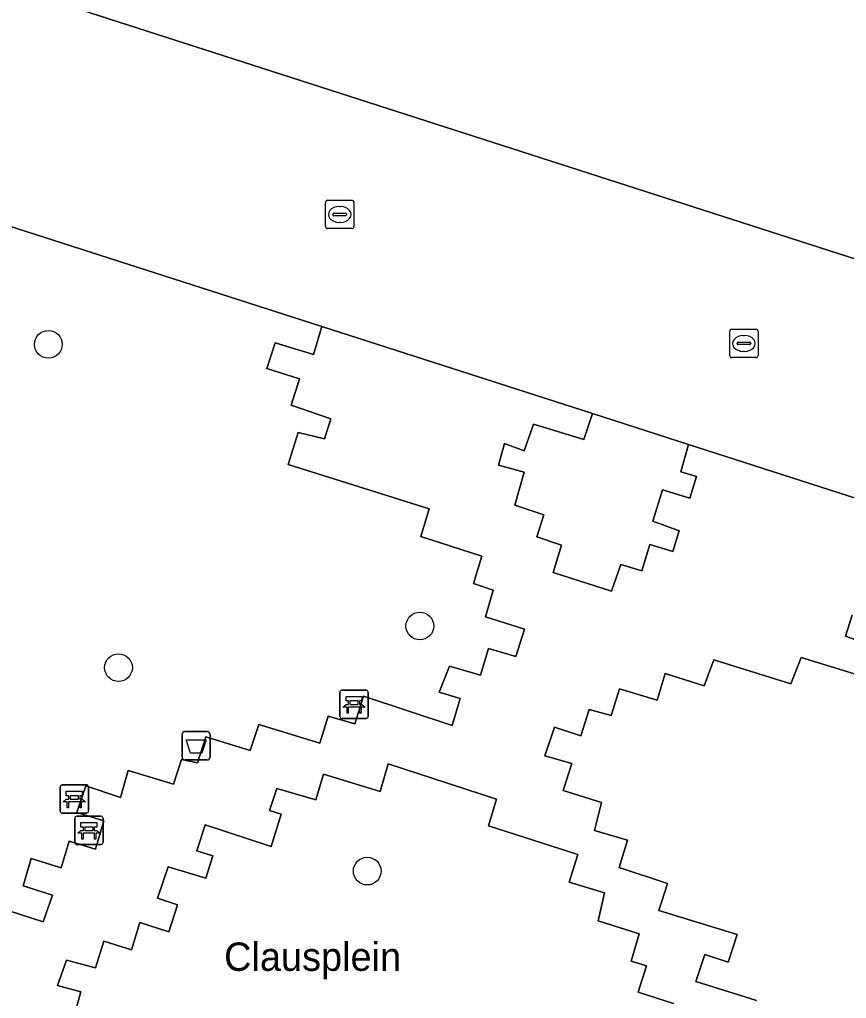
# Model space of a CAD drawing. Extents: x 160675 to 161153, y 383241 to 383714.
# Drawn here: x 161009.79 to 161038.96, y 383290.07 to 383324.6 of the extents above; entities that cross this region are included whole.
import ezdxf

# ---------------------------------------------------------------- set-up
doc = ezdxf.new("R2010")
doc.units = 0
for name, color, linetype in [('IMGEO_Afvalbak', 7, 'Continuous'), ('IMGEO_Bank', 7, 'Continuous'), ('IMGEO_Boom', 7, 'Continuous'), ('IMGEO_Groenvoorziening', 7, 'Continuous'), ('IMGEO_Kolk', 7, 'Continuous'), ('IMGEO_Openbare_ruimte_label', 7, 'Continuous'), ('IMGEO_Pand', 7, 'Continuous'), ('IMGEO_Voetpad_open', 7, 'Continuous')]:
    doc.layers.add(name, color=color, linetype=linetype)

msp = doc.modelspace()

# ---------------------------------------------------------------- linework, layer by layer
at = {"layer": 'IMGEO_Afvalbak'}
for p, q in [((161015.621, 383299.483), (161016.411, 383299.483)), ((161016.411, 383299.483), (161015.621, 383299.483)), ((161015.521, 383298.583), (161015.521, 383299.383)), ((161015.521, 383299.383), (161015.521, 383298.583)), ((161016.511, 383299.383), (161016.511, 383298.583)), ((161016.511, 383298.583), (161016.511, 383299.383)), ((161016.411, 383298.483), (161015.621, 383298.483)), ((161015.621, 383298.483), (161016.411, 383298.483))]:
    msp.add_line(p, q, dxfattribs=at)
msp.add_lwpolyline([(161015.664, 383299.197), (161016.368, 383299.197), (161016.219, 383298.727), (161015.813, 383298.727), (161015.664, 383299.197)], dxfattribs=at)
for centre, start, end in [((161015.621, 383299.383), 90, 180), ((161015.621, 383299.383), 90, 180), ((161016.411, 383299.383), 0, 90), ((161016.411, 383299.383), 360, 90), ((161015.621, 383298.583), 180, 270), ((161015.621, 383298.583), 180, 270), ((161016.411, 383298.583), 270, 0), ((161016.411, 383298.583), 270, 0)]:
    msp.add_arc(centre, 0.1, start, end, dxfattribs=at)
at = {"layer": 'IMGEO_Bank'}
for p, q in [((161021.086, 383300.021), (161021.086, 383300.862)), ((161021.086, 383300.862), (161021.086, 383300.021)), ((161021.161, 383300.946), (161022.002, 383300.946)), ((161022.002, 383300.946), (161021.161, 383300.946)), ((161022.086, 383300.871), (161022.086, 383300.03)), ((161022.086, 383300.03), (161022.086, 383300.871)), ((161021.395, 383300.452), (161021.395, 383300.558)), ((161021.439, 383300.558), (161021.439, 383300.452)), ((161021.727, 383300.564), (161021.445, 383300.564)), ((161021.445, 383300.446), (161021.727, 383300.446)), ((161021.733, 383300.452), (161021.733, 383300.558)), ((161021.777, 383300.558), (161021.777, 383300.452)), ((161021.783, 383300.344), (161021.39, 383300.344)), ((161022.011, 383299.946), (161021.17, 383299.946)), ((161021.17, 383299.946), (161022.011, 383299.946)), ((161011.218, 383296.681), (161011.218, 383297.522)), ((161011.218, 383297.522), (161011.218, 383296.681)), ((161011.293, 383297.606), (161012.134, 383297.606)), ((161012.134, 383297.606), (161011.293, 383297.606)), ((161012.218, 383297.531), (161012.218, 383296.69)), ((161012.218, 383296.69), (161012.218, 383297.531)), ((161011.915, 383297.004), (161011.522, 383297.004)), ((161011.527, 383297.112), (161011.527, 383297.218)), ((161011.571, 383297.218), (161011.571, 383297.112)), ((161011.859, 383297.224), (161011.577, 383297.224)), ((161011.577, 383297.106), (161011.859, 383297.106)), ((161011.865, 383297.112), (161011.865, 383297.218)), ((161011.909, 383297.218), (161011.909, 383297.112)), ((161012.143, 383296.606), (161011.302, 383296.606)), ((161011.302, 383296.606), (161012.143, 383296.606)), ((161011.733, 383295.576), (161011.733, 383296.417)), ((161011.733, 383296.417), (161011.733, 383295.576)), ((161011.808, 383296.501), (161012.649, 383296.501)), ((161012.649, 383296.501), (161011.808, 383296.501)), ((161012.733, 383296.426), (161012.733, 383295.585)), ((161012.733, 383295.585), (161012.733, 383296.426)), ((161012.042, 383296.007), (161012.042, 383296.113)), ((161012.086, 383296.113), (161012.086, 383296.007)), ((161012.374, 383296.119), (161012.092, 383296.119)), ((161012.092, 383296.001), (161012.374, 383296.001)), ((161012.38, 383296.007), (161012.38, 383296.113)), ((161012.424, 383296.113), (161012.424, 383296.007)), ((161012.43, 383295.899), (161012.037, 383295.899)), ((161012.658, 383295.501), (161011.817, 383295.501)), ((161011.817, 383295.501), (161012.658, 383295.501))]:
    msp.add_line(p, q, dxfattribs=at)
for points in [[(161021.333, 383300.344), (161021.191, 383300.344), (161021.303, 383300.446), (161021.389, 383300.446)], [(161021.389, 383300.564), (161021.303, 383300.564), (161021.303, 383300.725), (161021.866, 383300.725), (161021.866, 383300.564), (161021.783, 383300.564)], [(161021.783, 383300.446), (161021.866, 383300.446), (161021.978, 383300.344), (161021.839, 383300.344)], [(161021.383, 383300.337), (161021.383, 383300.13), (161021.34, 383300.13), (161021.34, 383300.337)], [(161021.833, 383300.337), (161021.833, 383300.13), (161021.789, 383300.13), (161021.789, 383300.337)], [(161011.521, 383297.224), (161011.435, 383297.224), (161011.435, 383297.385), (161011.998, 383297.385), (161011.998, 383297.224), (161011.915, 383297.224)], [(161011.465, 383297.004), (161011.323, 383297.004), (161011.435, 383297.106), (161011.521, 383297.106)], [(161011.515, 383296.997), (161011.515, 383296.79), (161011.472, 383296.79), (161011.472, 383296.997)], [(161011.915, 383297.106), (161011.998, 383297.106), (161012.11, 383297.004), (161011.971, 383297.004)], [(161011.965, 383296.997), (161011.965, 383296.79), (161011.921, 383296.79), (161011.921, 383296.997)], [(161011.98, 383295.899), (161011.838, 383295.899), (161011.95, 383296.001), (161012.036, 383296.001)], [(161012.036, 383296.119), (161011.95, 383296.119), (161011.95, 383296.28), (161012.513, 383296.28), (161012.513, 383296.119), (161012.43, 383296.119)], [(161012.43, 383296.001), (161012.513, 383296.001), (161012.625, 383295.899), (161012.486, 383295.899)], [(161012.03, 383295.892), (161012.03, 383295.685), (161011.987, 383295.685), (161011.987, 383295.892)], [(161012.48, 383295.892), (161012.48, 383295.685), (161012.436, 383295.685), (161012.436, 383295.892)]]:
    msp.add_lwpolyline(points, dxfattribs=at)
for centre, radius, start, end in [((161021.164, 383300.868), 0.0779, 92.4484, 184.2845), ((161021.164, 383300.868), 0.0779, 92.4484, 184.2845), ((161022.008, 383300.868), 0.0779, 2.4484, 94.2845), ((161022.008, 383300.868), 0.0779, 2.4484, 94.2845), ((161021.388, 383300.557), 0.00671, 2.8957, 87.1043), ((161021.388, 383300.453), 0.00671, 272.8957, 357.1043), ((161021.445, 383300.557), 0.00671, 92.8957, 177.1043), ((161021.445, 383300.453), 0.00671, 182.8957, 267.1043), ((161021.727, 383300.557), 0.00671, 2.8957, 87.1043), ((161021.727, 383300.453), 0.00671, 272.8957, 357.1043), ((161021.784, 383300.557), 0.00671, 92.8957, 177.1043), ((161021.784, 383300.453), 0.00671, 182.8957, 267.1043), ((161021.333, 383300.337), 0.00671, 2.8957, 87.1043), ((161021.39, 383300.337), 0.00671, 92.8957, 177.1043), ((161021.782, 383300.337), 0.00671, 2.8957, 87.1043), ((161021.839, 383300.337), 0.00671, 92.8957, 177.1043), ((161021.164, 383300.024), 0.0779, 182.4484, 274.2845), ((161021.164, 383300.024), 0.0779, 182.4484, 274.2845), ((161022.008, 383300.024), 0.0779, 272.4484, 4.2845), ((161022.008, 383300.024), 0.0779, 272.4484, 4.2845), ((161011.296, 383297.528), 0.0779, 92.4484, 184.2845), ((161011.296, 383297.528), 0.0779, 92.4484, 184.2845), ((161012.14, 383297.528), 0.0779, 2.4484, 94.2845), ((161012.14, 383297.528), 0.0779, 2.4484, 94.2845), ((161011.465, 383296.997), 0.00671, 2.8957, 87.1043), ((161011.522, 383296.997), 0.00671, 92.8957, 177.1043), ((161011.52, 383297.217), 0.00671, 2.8957, 87.1043), ((161011.52, 383297.113), 0.00671, 272.8957, 357.1043), ((161011.577, 383297.217), 0.00671, 92.8957, 177.1043), ((161011.577, 383297.113), 0.00671, 182.8957, 267.1043), ((161011.859, 383297.217), 0.00671, 2.8957, 87.1043), ((161011.859, 383297.113), 0.00671, 272.8957, 357.1043), ((161011.916, 383297.217), 0.00671, 92.8957, 177.1043), ((161011.916, 383297.113), 0.00671, 182.8957, 267.1043), ((161011.914, 383296.997), 0.00671, 2.8957, 87.1043), ((161011.971, 383296.997), 0.00671, 92.8957, 177.1043), ((161011.296, 383296.684), 0.0779, 182.4484, 274.2845), ((161011.296, 383296.684), 0.0779, 182.4484, 274.2845), ((161012.14, 383296.684), 0.0779, 272.4484, 4.2845), ((161012.14, 383296.684), 0.0779, 272.4484, 4.2845), ((161011.811, 383296.423), 0.0779, 92.4484, 184.2845), ((161011.811, 383296.423), 0.0779, 92.4484, 184.2845), ((161012.655, 383296.423), 0.0779, 2.4484, 94.2845), ((161012.655, 383296.423), 0.0779, 2.4484, 94.2845), ((161012.035, 383296.112), 0.00671, 2.8957, 87.1043), ((161012.035, 383296.008), 0.00671, 272.8957, 357.1043), ((161012.092, 383296.112), 0.00671, 92.8957, 177.1043), ((161012.092, 383296.008), 0.00671, 182.8957, 267.1043), ((161012.374, 383296.112), 0.00671, 2.8957, 87.1043), ((161012.374, 383296.008), 0.00671, 272.8957, 357.1043), ((161012.431, 383296.112), 0.00671, 92.8957, 177.1043), ((161012.431, 383296.008), 0.00671, 182.8957, 267.1043), ((161011.98, 383295.892), 0.00671, 2.8957, 87.1043), ((161012.037, 383295.892), 0.00671, 92.8957, 177.1043), ((161012.429, 383295.892), 0.00671, 2.8957, 87.1043), ((161012.486, 383295.892), 0.00671, 92.8957, 177.1043), ((161011.811, 383295.579), 0.0779, 182.4484, 274.2845), ((161011.811, 383295.579), 0.0779, 182.4484, 274.2845), ((161012.655, 383295.579), 0.0779, 272.4484, 4.2845), ((161012.655, 383295.579), 0.0779, 272.4484, 4.2845)]:
    msp.add_arc(centre, radius, start, end, dxfattribs=at)
at = {"layer": 'IMGEO_Boom'}
for centre in [(161010.8, 383313.141), (161023.908, 383303.206), (161013.277, 383301.742), (161022.051, 383294.563)]:
    msp.add_circle(centre, 0.489, dxfattribs=at)
at = {"layer": 'IMGEO_Groenvoorziening'}
for points in [[(161009.01, 383293.288), (161010.622, 383292.773), (161010.949, 383293.72), (161009.912, 383294.046), (161010.191, 383295.008), (161011.252, 383294.683), (161011.539, 383295.619), (161012.464, 383295.342), (161012.766, 383296.339), (161011.812, 383296.634), (161012.125, 383297.572), (161013.352, 383297.155), (161013.615, 383298.116), (161015.219, 383297.625), (161015.503, 383298.5), (161016.068, 383298.385), (161016.356, 383299.303), (161017.924, 383298.818), (161018.223, 383299.729), (161020.382, 383299.08), (161020.678, 383300.024), (161021.609, 383299.757), (161021.922, 383300.729), (161025.049, 383299.699), (161025.332, 383300.651), (161024.593, 383300.873), (161024.952, 383301.796), (161026.042, 383301.469), (161026.334, 383302.411), (161027.295, 383302.135), (161027.604, 383303.092), (161026.22, 383303.531), (161026.497, 383304.473), (161025.799, 383304.712), (161026.093, 383305.675), (161023.947, 383306.371), (161024.235, 383307.338), (161019.264, 383308.904), (161019.617, 383310.033), (161020.541, 383309.81), (161020.767, 383310.514), (161019.372, 383310.996), (161019.661, 383311.926), (161018.509, 383312.286), (161018.799, 383313.201), (161020.156, 383312.782), (161020.455, 383313.768), (161008.359, 383317.657)], [(161039.154, 383303.596), (161038.919, 383302.854), (161039.655, 383302.597)], [(161039.31, 383301.493), (161037.358, 383302.095), (161037, 383301.174), (161034.277, 383302.021), (161033.932, 383301.096), (161032.563, 383301.537), (161032.278, 383300.589), (161030.954, 383300.992), (161030.659, 383300.053), (161029.877, 383300.269), (161029.584, 383299.33), (161028.662, 383299.636), (161028.312, 383298.632), (161029.264, 383298.355), (161028.964, 383297.406), (161030.31, 383296.978), (161030.069, 383295.995), (161031.232, 383295.658), (161030.944, 383294.688), (161032.647, 383294.121), (161032.339, 383293.175), (161035.1, 383292.332), (161034.789, 383291.349), (161033.961, 383291.627), (161033.644, 383290.671), (161035.785, 383289.999)], [(161032.861, 383289.89), (161031.605, 383290.297), (161031.904, 383291.219), (161031.363, 383291.387), (161031.64, 383292.348), (161030.199, 383292.814), (161030.425, 383293.795), (161029.174, 383294.178), (161029.478, 383295.151), (161026.327, 383296.159), (161026.615, 383297.097), (161022.794, 383298.344), (161022.507, 383297.376), (161020.505, 383297.985), (161020.24, 383297.073), (161018.861, 383297.48), (161018.601, 383296.703), (161019.015, 383296.571), (161018.662, 383295.437), (161016.335, 383296.195), (161016.036, 383295.283), (161016.607, 383295.097), (161016.358, 383294.311), (161015.033, 383294.716), (161014.652, 383293.604), (161015.363, 383293.37), (161015.05, 383292.427), (161014.027, 383292.746), (161013.737, 383291.787), (161012.759, 383292.094), (161012.468, 383291.146), (161011.441, 383291.426), (161011.122, 383290.524), (161011.947, 383290.301), (161011.665, 383289.292)]]:
    msp.add_lwpolyline(points, dxfattribs=at)
msp.add_lwpolyline([(161033.388, 383309.609), (161029.994, 383310.701), (161029.691, 383309.783), (161027.916, 383310.325), (161027.583, 383309.39), (161026.889, 383309.648), (161026.684, 383308.883), (161027.588, 383308.632), (161027.262, 383307.47), (161028.281, 383307.126), (161028.038, 383306.357), (161028.907, 383306.061), (161028.611, 383305.098), (161030.672, 383304.434), (161030.992, 383305.374), (161031.735, 383305.158), (161032.024, 383306.08), (161032.831, 383305.832), (161033.061, 383306.57), (161032.129, 383306.903), (161032.471, 383308.012), (161033.431, 383307.723), (161033.666, 383308.484), (161033.111, 383308.651)], close=True, dxfattribs=at)
at = {"layer": 'IMGEO_Kolk'}
for p, q in [((161020.58, 383317.299), (161020.58, 383318.151)), ((161020.655, 383318.225), (161021.507, 383318.225)), ((161021.581, 383318.151), (161021.581, 383317.299)), ((161020.839, 383317.719), (161020.839, 383317.731)), ((161020.882, 383317.768), (161021.28, 383317.768)), ((161021.068, 383318.005), (161021.093, 383318.005)), ((161021.323, 383317.731), (161021.323, 383317.719)), ((161021.277, 383317.682), (161020.879, 383317.682)), ((161021.091, 383317.445), (161021.066, 383317.445)), ((161021.507, 383317.225), (161020.655, 383317.225)), ((161034.837, 383312.75), (161034.837, 383313.602)), ((161034.912, 383313.676), (161035.764, 383313.676)), ((161035.838, 383313.602), (161035.838, 383312.75)), ((161035.139, 383313.219), (161035.537, 383313.219)), ((161035.325, 383313.456), (161035.35, 383313.456)), ((161035.096, 383313.17), (161035.096, 383313.182)), ((161035.534, 383313.133), (161035.136, 383313.133)), ((161035.348, 383312.896), (161035.323, 383312.896)), ((161035.58, 383313.182), (161035.58, 383313.17)), ((161035.764, 383312.676), (161034.912, 383312.676))]:
    msp.add_line(p, q, dxfattribs=at)
for points in [[(161020.58, 383317.299), (161020.58, 383318.151)], [(161020.655, 383318.225), (161021.507, 383318.225)], [(161021.581, 383318.151), (161021.581, 383317.299)], [(161021.507, 383317.225), (161020.655, 383317.225)], [(161034.837, 383312.75), (161034.837, 383313.602)], [(161034.912, 383313.676), (161035.764, 383313.676)], [(161035.838, 383313.602), (161035.838, 383312.75)], [(161035.764, 383312.676), (161034.912, 383312.676)]]:
    msp.add_lwpolyline(points, dxfattribs=at)
for centre, radius, start, end in [((161020.657, 383318.149), 0.0765, 91.552, 178.448), ((161020.657, 383318.149), 0.0765, 91.552, 178.448), ((161021.505, 383318.149), 0.0765, 1.552, 88.448), ((161021.505, 383318.149), 0.0765, 1.552, 88.448), ((161020.879, 383317.728), 0.0403, 85.8775, 175.7526), ((161020.876, 383317.718), 0.0366, 178.938, 274.7102), ((161021.28, 383317.725), 0.043, 264.8664, 352.4533), ((161021.284, 383317.73), 0.0386, 1.7309, 96.639), ((161020.657, 383317.301), 0.0765, 181.552, 268.448), ((161020.657, 383317.301), 0.0765, 181.552, 268.448), ((161021.505, 383317.301), 0.0765, 271.552, 358.448), ((161021.505, 383317.301), 0.0765, 271.552, 358.448), ((161034.914, 383313.6), 0.0765, 91.552, 178.448), ((161034.914, 383313.6), 0.0765, 91.552, 178.448), ((161035.762, 383313.6), 0.0765, 1.552, 88.448), ((161035.762, 383313.6), 0.0765, 1.552, 88.448), ((161035.136, 383313.179), 0.0403, 85.8775, 175.7526), ((161035.541, 383313.181), 0.0386, 1.7309, 96.639), ((161035.133, 383313.169), 0.0366, 178.938, 274.7102), ((161035.537, 383313.176), 0.043, 264.8664, 352.4533), ((161034.914, 383312.752), 0.0765, 181.552, 268.448), ((161034.914, 383312.752), 0.0765, 181.552, 268.448), ((161035.762, 383312.752), 0.0765, 271.552, 358.448), ((161035.762, 383312.752), 0.0765, 271.552, 358.448)]:
    msp.add_arc(centre, radius, start, end, dxfattribs=at)
for centre, major_axis, ratio, start_param, end_param in [((161021.067, 383317.725), (-0.387, 0.002), 0.722429, 4.712389, 7.853982), ((161021.092, 383317.725), (-0.39, 0.002), 0.717154, 1.570796, 4.712389), ((161035.324, 383313.176), (-0.387, 0.002), 0.722429, 4.712389, 7.853982), ((161035.349, 383313.176), (-0.39, 0.002), 0.717154, 1.570796, 4.712389)]:
    msp.add_ellipse(centre, major_axis=major_axis, ratio=ratio, start_param=start_param, end_param=end_param, dxfattribs=at)
at = {"layer": 'IMGEO_Pand'}
msp.add_lwpolyline([(160982.34, 383300.282), (160989.622, 383299.281), (160990.405, 383301.74), (160994.422, 383300.461), (161000, 383317.976), (161003.126, 383327.791), (161044.076, 383314.613), (161056.802, 383310.518), (161068.681, 383306.695), (161070.205, 383311.433), (161071.867, 383310.899), (161075.639, 383322.641), (161073.926, 383323.193), (161075.413, 383327.845)], dxfattribs=at)
at = {"layer": 'IMGEO_Voetpad_open'}
for points in [[(161044.076, 383314.613), (161003.126, 383327.791), (161000, 383317.976), (160994.422, 383300.461), (160992.588, 383294.531), (160992.503, 383294.205), (160992.079, 383292.966), (160992.001, 383292.648), (160990.482, 383287.946), (160996.111, 383286.133), (160995.794, 383285.133), (160991.53, 383286.518), (160985.535, 383267.741), (160987.295, 383264.611), (160987.726, 383263.594), (160987.9, 383263.299)], [(160988.155, 383261.661), (160988.114, 383261.392), (160988.425, 383261.349), (160990.337, 383261.053), (160991.153, 383263.864), (160998.889, 383288.05), (160999.79, 383290.864), (161008.359, 383317.657), (161020.455, 383313.768), (161029.994, 383310.701), (161033.388, 383309.609), (161050.91, 383303.976), (161057.751, 383301.776), (161072.558, 383297.57), (161074.2, 383297.033), (161075.504, 383289.465)], [(161050.91, 383303.976), (161033.388, 383309.609), (161033.111, 383308.651), (161033.666, 383308.484), (161033.431, 383307.723), (161032.471, 383308.012), (161032.129, 383306.903), (161033.061, 383306.57), (161032.831, 383305.832), (161032.024, 383306.08), (161031.735, 383305.158), (161030.992, 383305.374), (161030.672, 383304.434), (161028.611, 383305.098), (161028.907, 383306.061), (161028.038, 383306.357), (161028.281, 383307.126), (161027.262, 383307.47), (161027.588, 383308.632), (161026.684, 383308.883), (161026.889, 383309.648), (161027.583, 383309.39), (161027.916, 383310.325), (161029.691, 383309.783), (161029.994, 383310.701), (161020.455, 383313.768), (161020.156, 383312.782), (161018.799, 383313.201), (161018.509, 383312.286), (161019.661, 383311.926), (161019.372, 383310.996), (161020.767, 383310.514), (161020.541, 383309.81), (161019.617, 383310.033), (161019.264, 383308.904), (161024.235, 383307.338), (161023.947, 383306.371), (161026.093, 383305.675), (161025.799, 383304.712), (161026.497, 383304.473), (161026.22, 383303.531), (161027.604, 383303.092), (161027.295, 383302.135), (161026.334, 383302.411), (161026.042, 383301.469), (161024.952, 383301.796), (161024.593, 383300.873), (161025.332, 383300.651), (161025.049, 383299.699), (161021.922, 383300.729), (161021.609, 383299.757), (161020.678, 383300.024), (161020.382, 383299.08), (161018.223, 383299.729), (161017.924, 383298.818), (161016.356, 383299.303), (161016.068, 383298.385), (161015.503, 383298.5), (161015.219, 383297.625), (161013.615, 383298.116), (161013.352, 383297.155), (161012.125, 383297.572), (161011.812, 383296.634), (161012.766, 383296.339), (161012.464, 383295.342), (161011.539, 383295.619), (161011.252, 383294.683), (161010.191, 383295.008), (161009.912, 383294.046), (161010.949, 383293.72), (161010.622, 383292.773), (161009.01, 383293.288)], [(161039.655, 383302.597), (161038.919, 383302.854), (161039.154, 383303.596)], [(161035.785, 383289.999), (161033.644, 383290.671), (161033.961, 383291.627), (161034.789, 383291.349), (161035.1, 383292.332), (161032.339, 383293.175), (161032.647, 383294.121), (161030.944, 383294.688), (161031.232, 383295.658), (161030.069, 383295.995), (161030.31, 383296.978), (161028.964, 383297.406), (161029.264, 383298.355), (161028.312, 383298.632), (161028.662, 383299.636), (161029.584, 383299.33), (161029.877, 383300.269), (161030.659, 383300.053), (161030.954, 383300.992), (161032.278, 383300.589), (161032.563, 383301.537), (161033.932, 383301.096), (161034.277, 383302.021), (161037, 383301.174), (161037.358, 383302.095), (161039.31, 383301.493)], [(161011.665, 383289.292), (161011.947, 383290.301), (161011.122, 383290.524), (161011.441, 383291.426), (161012.468, 383291.146), (161012.759, 383292.094), (161013.737, 383291.787), (161014.027, 383292.746), (161015.05, 383292.427), (161015.363, 383293.37), (161014.652, 383293.604), (161015.033, 383294.716), (161016.358, 383294.311), (161016.607, 383295.097), (161016.036, 383295.283), (161016.335, 383296.195), (161018.662, 383295.437), (161019.015, 383296.571), (161018.601, 383296.703), (161018.861, 383297.48), (161020.24, 383297.073), (161020.505, 383297.985), (161022.507, 383297.376), (161022.794, 383298.344), (161026.615, 383297.097), (161026.327, 383296.159), (161029.478, 383295.151), (161029.174, 383294.178), (161030.425, 383293.795), (161030.199, 383292.814), (161031.64, 383292.348), (161031.363, 383291.387), (161031.904, 383291.219), (161031.605, 383290.297), (161032.861, 383289.89)]]:
    msp.add_lwpolyline(points, dxfattribs=at)

# ---------------------------------------------------------------- texts
at = {"layer": 'IMGEO_Openbare_ruimte_label'}
msp.add_text('Clausplein', height=1, dxfattribs=at).set_placement((161017.003, 383291.045))

doc.saveas('drawing.dxf')
